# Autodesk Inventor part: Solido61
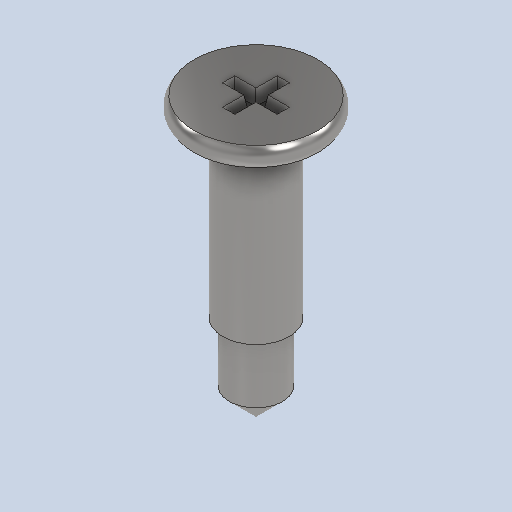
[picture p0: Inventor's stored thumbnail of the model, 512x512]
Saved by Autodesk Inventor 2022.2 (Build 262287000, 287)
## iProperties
Created: 2024-10
Part Number: Solido61
Material: Acciaio inossidabile
Document SubType Name: Modeling
Designer: 18907419
Density: 8 g/cm^3
Appearance: Default
Author: 18907419
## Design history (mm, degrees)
feature "Solido61"
node "Solido1"
